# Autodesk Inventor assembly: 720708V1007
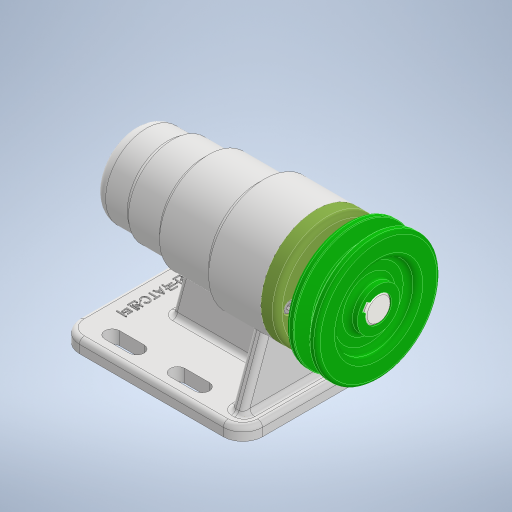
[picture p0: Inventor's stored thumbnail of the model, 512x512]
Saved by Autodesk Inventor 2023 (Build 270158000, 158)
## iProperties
Created: 2022-07
Part Number: 720708V1007
Document SubType Name: Assembly
Designer: owner
Author: owner
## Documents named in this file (12)
- C:\Users\owner\Desktop\720708V1007\720708V1007.iam
- C:\Users\owner\Desktop\720708V1007\본체.ipt
- C:\Users\owner\Desktop\720708V1007\V벨트풀리.ipt
- C:\Users\owner\Desktop\720708V1007\멈춤나사 M3.ipt
- C:\Users\owner\Desktop\720708V1007\베어링 6004.ipt
- C:\Users\owner\Desktop\720708V1007\베어링 51202.ipt
- C:\Users\owner\Desktop\720708V1007\볼트 M4.ipt
- C:\Users\owner\Desktop\720708V1007\어댑터슬리브.ipt
- C:\Users\owner\Desktop\720708V1007\오일 실 20x35x7.ipt
- C:\Users\owner\Desktop\720708V1007\축.ipt
- C:\Users\owner\Desktop\720708V1007\커버.ipt
- C:\Users\owner\Desktop\720708V1007\키 5x5.ipt
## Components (1 placed, 1 different names)
1. V벨트풀리:1
